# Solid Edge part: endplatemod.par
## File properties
Author: Deepak Maini
Template: NORMENG.PAR
Last saved by: Robert a Rhodes jr
Revision: 1
Application: Solid Edge
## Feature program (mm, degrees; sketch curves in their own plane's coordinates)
sketch for "unnamed Protrusion 1" plane through (0, 0, 0) normal (0, 0, 1) x-axis (1, 0, 0)
  line (-50.8, 46.0858) -> (-50.8, -55.5142)
  line (-50.8, -55.5142) -> (50.8, -55.5142)
  line (50.8, -55.5142) -> (50.8, 46.0858)
  line (50.8, 46.0858) -> (-50.8, 46.0858)
extrude "unnamed Protrusion 1" add finite 12.7 along +normal
sketch for "unnamed Hole 1" plane through (0, -4.7142, 12.7) normal (0, 0, 1) x-axis (1, 0, 0)
  hole centre (-38.1, -38.1) bore radius 3.175
hole "unnamed Hole 1" through
sketch for "unnamed Hole 2" plane through (0, -4.7142, 12.7) normal (0, 0, 1) x-axis (1, 0, 0)
  hole centre (38.1, -38.1) bore radius 3.175
hole "unnamed Hole 2" through
sketch for "unnamed Hole 3" plane through (0, -4.7142, 12.7) normal (0, 0, 1) x-axis (1, 0, 0)
  hole centre (38.1, 38.1) bore radius 3.175
hole "unnamed Hole 3" through
sketch for "unnamed Hole 4" plane through (0, -4.7142, 12.7) normal (0, 0, 1) x-axis (1, 0, 0)
  hole centre (-38.1, 38.1) bore radius 3.175
  dimension (linear) = 38.1
hole "unnamed Hole 4" through
pattern "unnamed Pattern 1" of "unnamed Hole 1", "unnamed Hole 2", "unnamed Hole 3", "unnamed Hole 4"
sketch for "unnamed Hole 5" plane through (0, -4.7142, 12.7) normal (0, 0, 1) x-axis (1, 0, 0)
  hole centre (0, 0) bore radius 12.7
hole "unnamed Hole 5" through
sketch for "unnamed Hole 6" plane through (0, -4.7142, 12.7) normal (0, 0, 1) x-axis (1, 0, 0)
  hole centre (-20.6375, 0) bore radius 2.3812
  dimension (linear) = 20.6375
hole "unnamed Hole 6" through
pattern "unnamed Pattern 2" of "unnamed Hole 6"
pattern "unnamed Pattern 3"
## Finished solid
Body 1: solid body, 15 faces, 30 edges, 8 vertices.
  Faces by surface: cylinder 9, plane 6
  Edges by curve: circle 18, line 12
Bounding box of the edges (mm): 101.600 x 101.600 x 12.700, from (-50.8, -55.5142, 0) to (50.8, 46.0858, 12.7).
Cylindrical faces by radius (mm): R2.3812 x4, R3.175 x4, R12.7 x1
Planar faces by outward normal: +x 1, +y 1, +z 1, -x 1, -y 1, -z 1
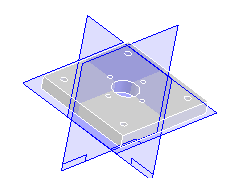
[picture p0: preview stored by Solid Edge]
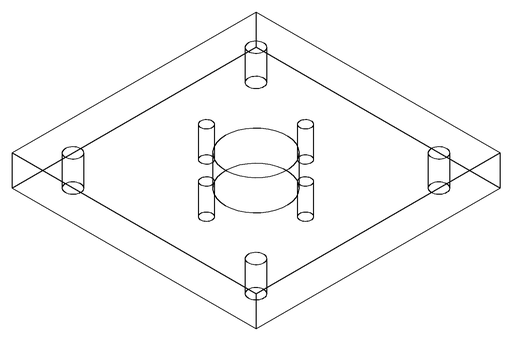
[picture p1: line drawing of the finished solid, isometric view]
